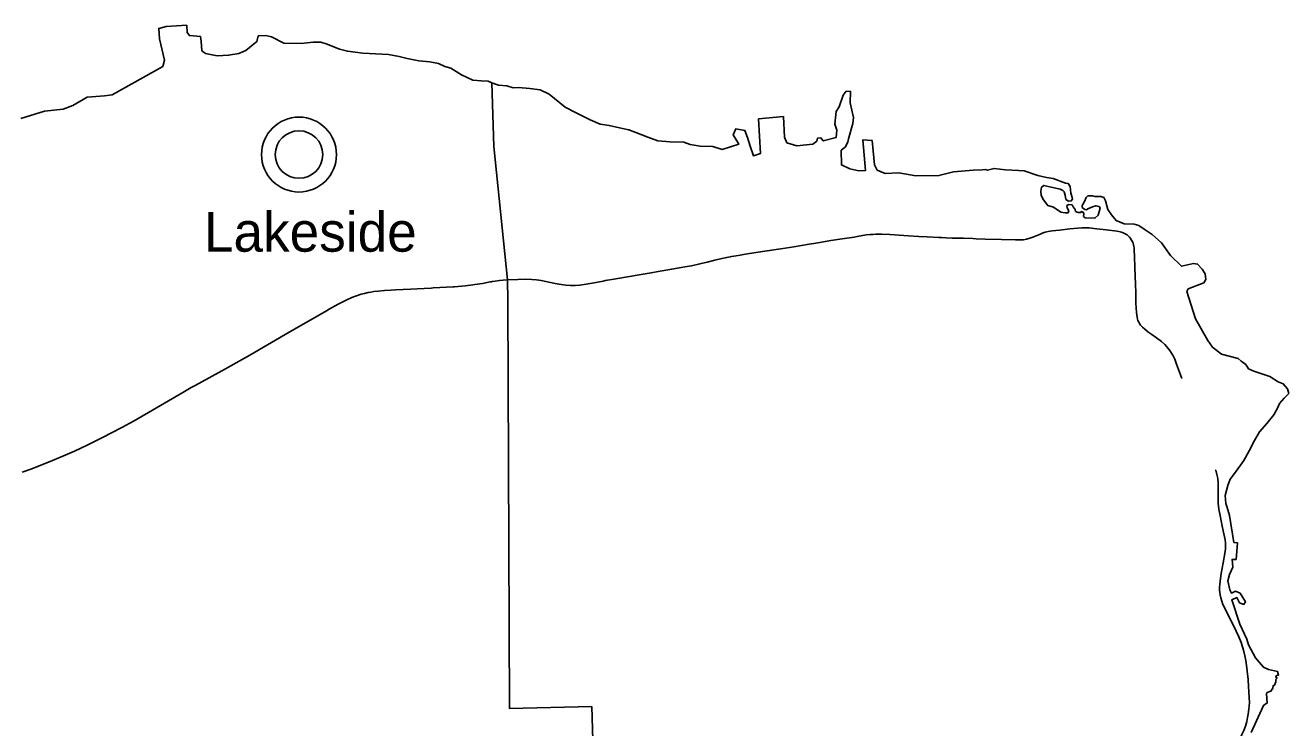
# Model space of a CAD drawing. Extents: x -82 to 873, y 0 to 440.
# Drawn here: x 541.88 to 574.98, y 185.82 to 204.25 of the extents above; entities that cross this region are included whole.
import ezdxf

# ---------------------------------------------------------------- set-up
doc = ezdxf.new("R2010")
doc.units = 0
for name, color, linetype in [('DV_X_Corp_Line', 7, 'Continuous'), ('GM_X_County', 7, 'Continuous'), ('GM_X_Interstate_Route', 7, 'Continuous')]:
    doc.layers.add(name, color=color, linetype=linetype)

msp = doc.modelspace()

# ---------------------------------------------------------------- linework, layer by layer
at = {"layer": 'DV_X_Corp_Line'}
msp.add_lwpolyline([(557.062, 174.811), (556.722, 186.379), (554.569, 186.327), (554.518, 197.04), (554.512, 197.569), (554.155, 201.067), (554.101, 202.741), (554.274, 202.678), (554.494, 202.663), (554.66, 202.61), (554.799, 202.614), (555.096, 202.593), (555.369, 202.557), (555.607, 202.437), (556.026, 202.096), (556.309, 201.954), (556.675, 201.763), (556.941, 201.653), (557.175, 201.621), (557.529, 201.536), (557.692, 201.504), (557.874, 201.437), (558.192, 201.316), (558.455, 201.217), (558.774, 201.192), (559.129, 201.185), (559.295, 201.118), (559.561, 201.079), (559.891, 201.072), (560.139, 200.99), (560.572, 201.125), (560.43, 201.377), (560.494, 201.529), (560.735, 201.49), (560.806, 201.306), (560.87, 201.079), (560.955, 200.827), (561.139, 200.88), (561.094, 201.789), (561.742, 201.852), (561.774, 201.316), (561.834, 201.168), (562.095, 201.086), (562.512, 201.125), (562.618, 201.21), (562.639, 201.288), (562.724, 201.292), (562.788, 201.214), (563.127, 201.307), (563.146, 201.494), (563.086, 201.653), (563.121, 201.99), (563.2, 202.104), (563.309, 202.412), (563.391, 202.519), (563.504, 202.512), (563.494, 202.21), (563.575, 201.827), (563.558, 201.675), (563.444, 201.267), (563.434, 201.185), (563.359, 201.051), (563.26, 200.969), (563.263, 200.586), (563.48, 200.48), (563.721, 200.43), (563.891, 200.434), (563.827, 201.246), (564.072, 201.224), (564.129, 200.583), (564.203, 200.448), (564.412, 200.356), (564.767, 200.373), (565.214, 200.299), (565.817, 200.306), (566.196, 200.402), (566.714, 200.445), (566.952, 200.452), (567.03, 200.462), (567.093, 200.448), (567.264, 200.491), (567.561, 200.452), (567.905, 200.438), (568.051, 200.43), (568.409, 200.306), (568.636, 200.257), (568.81, 200.228), (569.136, 200.104), (569.207, 200.097), (569.26, 200.023), (569.274, 199.845), (569.31, 199.732), (569.317, 199.689), (569.285, 199.64), (569.211, 199.633), (569.147, 199.682), (569.125, 199.789), (569.101, 199.877), (569.069, 199.913), (568.991, 199.948), (568.569, 200.048), (568.508, 200.001), (568.484, 199.895), (568.498, 199.782), (568.554, 199.672), (568.668, 199.523), (568.817, 199.477), (569.015, 199.342), (569.129, 199.328), (569.196, 199.328), (569.218, 199.363), (569.203, 199.413), (569.175, 199.455), (569.172, 199.519), (569.225, 199.544), (569.306, 199.54), (569.335, 199.487), (569.384, 199.413), (569.398, 199.367), (569.466, 199.335), (569.537, 199.338), (569.555, 199.367), (569.601, 199.342), (569.618, 199.299), (569.608, 199.232), (569.654, 199.197), (569.906, 199.186), (569.987, 199.271), (570.044, 199.452), (570.016, 199.491), (569.93, 199.512), (569.838, 199.484), (569.721, 199.434), (569.686, 199.409), (569.64, 199.416), (569.572, 199.47), (569.569, 199.516), (569.629, 199.626), (569.675, 199.728), (569.721, 199.771), (569.842, 199.771), (569.902, 199.753), (569.969, 199.753), (570.058, 199.76), (570.143, 199.728), (570.179, 199.643), (570.242, 199.413), (570.342, 199.275), (570.462, 199.129), (570.672, 199.041), (570.938, 199.03), (571.058, 198.995), (571.2, 198.899), (571.409, 198.757), (571.65, 198.537), (571.888, 198.207), (572.172, 197.927), (572.491, 197.998), (572.597, 197.984), (572.718, 197.853), (572.796, 197.725), (572.814, 197.576), (572.76, 197.488), (572.353, 197.331), (572.31, 197.268), (572.544, 196.544), (572.863, 195.984), (572.984, 195.807), (573.223, 195.623), (573.658, 195.505), (573.739, 195.438), (573.856, 195.353), (573.931, 195.239), (574.066, 195.179), (574.488, 195.034), (574.704, 194.892), (574.842, 194.846), (574.949, 194.715), (574.984, 194.587), (574.867, 194.466), (574.739, 194.324), (574.691, 194.202), (574.594, 194.034), (574.413, 193.807), (574.222, 193.583), (574.091, 193.353), (573.945, 193.09), (573.807, 192.831), (573.56, 192.488), (573.446, 192.34), (573.385, 192.178), (573.321, 191.914), (573.334, 191.709), (573.374, 191.599), (573.428, 191.391), (573.548, 190.685), (573.641, 190.677), (573.604, 190.239), (573.5, 190.237), (573.521, 190.034), (573.43, 189.842), (573.385, 189.68), (573.441, 189.442), (573.481, 189.354), (573.59, 189.405), (573.708, 189.354), (573.852, 189.13), (573.804, 189.056), (573.694, 189.098), (573.625, 189.237), (573.492, 189.178), (573.7, 188.544), (573.889, 188.146), (573.932, 187.999), (574.111, 187.661), (574.321, 187.411), (574.452, 187.352), (574.692, 187.299), (574.718, 187.203), (574.665, 187.195), (574.644, 187.147), (574.678, 187.125), (574.644, 187.088), (574.649, 187.027), (574.609, 186.939), (574.572, 186.925), (574.567, 186.864), (574.516, 186.784), (574.423, 186.752), (574.399, 186.709), (574.42, 186.475), (574.324, 186.411), (574.003, 185.702)], dxfattribs=at)
for radius in [0.982, 0.623]:
    msp.add_circle((549.049, 200.856), radius, dxfattribs=at)
at = {"layer": 'GM_X_County'}
msp.add_lwpolyline([(574.003, 185.702), (574.324, 186.411), (574.42, 186.475), (574.399, 186.709), (574.423, 186.752), (574.516, 186.784), (574.567, 186.864), (574.572, 186.925), (574.609, 186.939), (574.649, 187.027), (574.644, 187.088), (574.678, 187.125), (574.644, 187.147), (574.665, 187.195), (574.718, 187.203), (574.692, 187.299), (574.452, 187.352), (574.321, 187.411), (574.111, 187.661), (573.932, 187.999), (573.889, 188.146), (573.7, 188.544), (573.492, 189.178), (573.625, 189.237), (573.694, 189.098), (573.804, 189.056), (573.852, 189.13), (573.708, 189.354), (573.59, 189.405), (573.481, 189.354), (573.441, 189.442), (573.385, 189.68), (573.43, 189.842), (573.521, 190.034), (573.5, 190.237), (573.604, 190.239), (573.641, 190.677), (573.548, 190.685), (573.428, 191.391), (573.374, 191.599), (573.334, 191.709), (573.321, 191.914), (573.385, 192.178), (573.446, 192.34), (573.56, 192.488), (573.807, 192.831), (573.945, 193.09), (574.091, 193.353), (574.222, 193.583), (574.413, 193.807), (574.594, 194.034), (574.691, 194.202), (574.739, 194.324), (574.867, 194.466), (574.984, 194.587), (574.949, 194.715), (574.842, 194.846), (574.704, 194.892), (574.488, 195.034), (574.066, 195.179), (573.931, 195.239), (573.856, 195.353), (573.739, 195.438), (573.658, 195.505), (573.223, 195.623), (572.984, 195.807), (572.863, 195.984), (572.544, 196.544), (572.31, 197.268), (572.353, 197.331), (572.76, 197.488), (572.814, 197.576), (572.796, 197.725), (572.718, 197.853), (572.597, 197.984), (572.491, 197.998), (572.172, 197.927), (571.888, 198.207), (571.65, 198.537), (571.409, 198.757), (571.2, 198.899), (571.058, 198.995), (570.938, 199.03), (570.672, 199.041), (570.462, 199.129), (570.342, 199.275), (570.242, 199.413), (570.179, 199.643), (570.143, 199.728), (570.058, 199.76), (569.969, 199.753), (569.902, 199.753), (569.842, 199.771), (569.721, 199.771), (569.675, 199.728), (569.629, 199.626), (569.569, 199.516), (569.572, 199.47), (569.64, 199.416), (569.686, 199.409), (569.721, 199.434), (569.838, 199.484), (569.93, 199.512), (570.016, 199.491), (570.044, 199.452), (569.987, 199.271), (569.906, 199.186), (569.654, 199.197), (569.608, 199.232), (569.618, 199.299), (569.601, 199.342), (569.555, 199.367), (569.537, 199.338), (569.466, 199.335), (569.398, 199.367), (569.384, 199.413), (569.335, 199.487), (569.306, 199.54), (569.225, 199.544), (569.172, 199.519), (569.175, 199.455), (569.203, 199.413), (569.218, 199.363), (569.196, 199.328), (569.129, 199.328), (569.015, 199.342), (568.817, 199.477), (568.668, 199.523), (568.554, 199.672), (568.498, 199.782), (568.484, 199.895), (568.508, 200.001), (568.569, 200.048), (568.991, 199.948), (569.069, 199.913), (569.101, 199.877), (569.125, 199.789), (569.147, 199.682), (569.211, 199.633), (569.285, 199.64), (569.317, 199.689), (569.31, 199.732), (569.274, 199.845), (569.26, 200.023), (569.207, 200.097), (569.136, 200.104), (568.81, 200.228), (568.636, 200.257), (568.409, 200.306), (568.051, 200.43), (567.905, 200.438), (567.561, 200.452), (567.264, 200.491), (567.093, 200.448), (567.03, 200.462), (566.952, 200.452), (566.714, 200.445), (566.196, 200.402), (565.817, 200.306), (565.214, 200.299), (564.767, 200.373), (564.412, 200.356), (564.203, 200.448), (564.129, 200.583), (564.072, 201.224), (563.827, 201.246), (563.891, 200.434), (563.721, 200.43), (563.48, 200.48), (563.263, 200.586), (563.26, 200.969), (563.359, 201.051), (563.434, 201.185), (563.444, 201.267), (563.558, 201.675), (563.575, 201.827), (563.494, 202.21), (563.504, 202.512), (563.391, 202.519), (563.309, 202.412), (563.2, 202.104), (563.121, 201.99), (563.086, 201.653), (563.146, 201.494), (563.127, 201.307), (562.788, 201.214), (562.724, 201.292), (562.639, 201.288), (562.618, 201.21), (562.512, 201.125), (562.095, 201.086), (561.834, 201.168), (561.774, 201.316), (561.742, 201.852), (561.094, 201.789), (561.139, 200.88), (560.955, 200.827), (560.87, 201.079), (560.806, 201.306), (560.735, 201.49), (560.494, 201.529), (560.43, 201.377), (560.572, 201.125), (560.139, 200.99), (559.891, 201.072), (559.561, 201.079), (559.295, 201.118), (559.129, 201.185), (558.774, 201.192), (558.455, 201.217), (558.192, 201.316), (557.874, 201.437), (557.692, 201.504), (557.529, 201.536), (557.175, 201.621), (556.941, 201.653), (556.675, 201.763), (556.309, 201.954), (556.026, 202.096), (555.607, 202.437), (555.369, 202.557), (555.096, 202.593), (554.799, 202.614), (554.66, 202.61), (554.494, 202.663), (554.274, 202.678), (554.101, 202.741), (554.004, 202.777), (553.827, 202.787), (553.607, 202.809), (553.309, 202.951), (553.025, 203.123), (552.873, 203.163), (552.703, 203.248), (552.476, 203.284), (552.185, 203.316), (551.887, 203.372), (551.671, 203.429), (551.391, 203.479), (551.057, 203.5), (550.724, 203.514), (550.316, 203.564), (550.11, 203.624), (549.784, 203.748), (549.617, 203.801), (549.419, 203.801), (549.107, 203.766), (548.653, 203.776), (548.33, 203.943), (548.178, 203.978), (547.983, 203.968), (547.947, 203.819), (547.66, 203.585), (547.476, 203.507), (547.206, 203.461), (546.905, 203.446), (546.603, 203.503), (546.5, 203.578), (546.486, 203.833), (546.465, 203.957), (546.178, 203.978), (546.121, 204.056), (546.107, 204.248), (545.564, 204.219), (545.373, 204.166), (545.398, 203.89), (545.529, 203.329), (545.483, 203.166), (544.153, 202.425), (543.955, 202.395), (543.5, 202.365), (543.125, 202.141), (542.866, 202.049), (542.379, 201.993), (541.756, 201.801)], dxfattribs=at)
at = {"layer": 'GM_X_Interstate_Route'}
for points in [[(557.76, 197.67), (557.909, 197.695), (558.274, 197.758), (558.457, 197.79), (558.816, 197.853), (559.067, 197.897), (559.16, 197.913), (559.331, 197.942), (559.553, 197.988), (559.743, 198.034), (559.943, 198.084), (560.129, 198.13), (560.258, 198.159), (560.389, 198.185), (560.612, 198.22), (560.738, 198.241), (561.252, 198.326), (561.673, 198.384), (562.013, 198.44), (562.418, 198.504), (562.539, 198.524), (562.642, 198.541), (562.987, 198.6), (563.283, 198.646), (563.594, 198.693), (563.675, 198.706), (563.915, 198.748), (564.015, 198.762), (564.089, 198.764), (564.162, 198.766), (564.325, 198.768), (564.53, 198.757), (564.776, 198.74), (565.022, 198.724), (565.292, 198.708), (565.514, 198.695), (565.819, 198.68), (565.883, 198.677), (566.005, 198.671), (566.162, 198.667), (566.28, 198.665), (566.355, 198.664), (566.466, 198.662), (566.708, 198.653), (566.795, 198.649), (567.031, 198.641), (567.457, 198.627), (567.826, 198.616), (567.95, 198.616), (568.033, 198.622), (568.115, 198.636), (568.202, 198.664), (568.276, 198.692), (568.495, 198.78), (568.502, 198.782)], [(568.502, 198.782), (568.553, 198.801), (568.604, 198.817), (568.679, 198.835), (568.787, 198.852), (568.979, 198.876), (569.251, 198.906), (569.458, 198.926), (569.561, 198.934), (569.66, 198.938), (569.754, 198.933), (569.875, 198.919), (570.202, 198.882), (570.486, 198.844), (570.566, 198.829), (570.604, 198.818), (570.642, 198.805), (570.679, 198.788), (570.714, 198.769), (570.747, 198.747), (570.778, 198.722), (570.809, 198.691), (570.839, 198.654), (570.865, 198.615), (570.89, 198.569), (570.904, 198.531), (570.915, 198.49), (570.925, 198.442), (570.931, 198.406), (570.937, 198.339), (570.944, 198.19), (570.953, 197.896), (570.962, 197.677), (570.967, 197.443), (570.974, 197.249), (570.981, 196.961), (570.995, 196.714), (571.001, 196.651), (571.01, 196.592), (571.021, 196.541), (571.034, 196.5), (571.052, 196.46), (571.071, 196.425), (571.101, 196.385), (571.155, 196.328), (571.215, 196.274), (571.284, 196.219), (571.296, 196.21), (571.396, 196.139), (571.518, 196.053), (571.647, 195.952), (571.738, 195.871), (571.793, 195.811), (571.87, 195.716), (571.916, 195.65), (571.957, 195.574), (571.996, 195.486), (572.046, 195.357), (572.148, 195.083), (572.186, 194.981)], [(554.299, 197.551), (554.305, 197.552), (554.397, 197.56), (554.512, 197.569), (554.784, 197.583), (554.989, 197.585), (555.153, 197.58), (555.275, 197.57), (555.396, 197.553), (555.758, 197.478), (555.92, 197.45), (556.043, 197.43), (556.166, 197.421), (556.288, 197.421), (556.409, 197.432), (556.578, 197.458), (556.78, 197.491), (557.02, 197.539), (557.079, 197.55), (557.302, 197.592), (557.76, 197.67)], [(549.823, 196.791), (550.078, 196.933), (550.246, 197.02), (550.322, 197.058), (550.396, 197.091), (550.414, 197.098), (550.476, 197.123), (550.556, 197.151), (550.681, 197.191), (550.764, 197.214), (550.865, 197.237), (550.935, 197.25), (551.006, 197.261), (551.123, 197.276), (551.287, 197.292), (551.454, 197.302), (551.574, 197.308), (551.979, 197.325), (552.148, 197.332), (552.516, 197.354), (552.566, 197.357), (553.09, 197.389), (553.125, 197.391), (553.411, 197.416), (553.601, 197.439), (553.654, 197.445), (553.857, 197.478), (554.061, 197.515), (554.083, 197.52), (554.111, 197.525), (554.192, 197.538), (554.299, 197.551)], [(541.793, 192.526), (542.024, 192.609), (542.483, 192.787), (542.862, 192.944), (543.162, 193.076), (543.496, 193.233), (543.899, 193.434), (544.409, 193.697), (544.733, 193.875), (546.008, 194.62), (546.225, 194.743), (546.329, 194.802), (547.12, 195.237), (547.763, 195.599), (548.793, 196.194), (549.787, 196.77), (549.823, 196.791)], [(573.069, 192.583), (573.071, 192.575), (573.101, 192.464), (573.122, 192.362), (573.134, 192.251), (573.134, 192.13), (573.134, 191.952), (573.132, 191.825), (573.134, 191.714), (573.153, 191.558), (573.185, 191.394), (573.243, 191.114), (573.285, 190.909), (573.315, 190.756), (573.326, 190.662), (573.329, 190.615), (573.33, 190.563), (573.329, 190.52), (573.321, 190.451), (573.312, 190.395), (573.268, 190.152), (573.218, 189.867), (573.185, 189.67), (573.176, 189.587), (573.168, 189.505), (573.172, 189.431), (573.176, 189.372), (573.186, 189.305), (573.203, 189.228), (573.227, 189.146), (573.26, 189.06), (573.385, 188.801), (573.604, 188.359), (573.673, 188.211), (573.735, 188.06), (573.777, 187.945), (573.784, 187.919), (573.811, 187.827), (573.837, 187.708), (573.857, 187.587), (573.892, 187.322)], [(573.892, 187.322), (573.895, 187.302), (573.917, 187.099), (573.933, 186.895), (573.941, 186.772), (573.95, 186.609), (573.952, 186.487), (573.947, 186.392), (573.941, 186.318), (573.934, 186.244), (573.925, 186.179), (573.908, 186.09), (573.884, 185.989), (573.847, 185.868), (573.804, 185.754), (573.755, 185.642), (573.699, 185.532), (573.617, 185.391), (573.528, 185.254), (573.405, 185.077)]]:
    msp.add_lwpolyline(points, dxfattribs=at)

# ---------------------------------------------------------------- texts
at = {"layer": 'DV_X_Corp_Line'}
msp.add_text('Lakeside', height=1.0417, rotation=0.005, dxfattribs=at).set_placement((546.558, 198.309))

doc.saveas('drawing.dxf')
